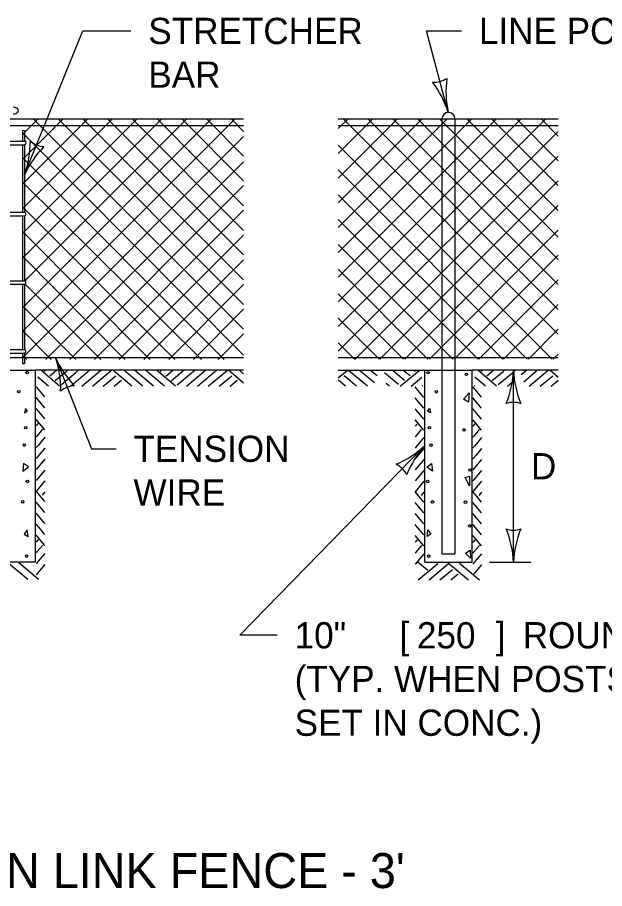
# Model space of a CAD drawing. Extents: x 49973.1 to 50021, y 49987.6 to 50015.4.
# Drawn here: x 49975.152 to 49976.495, y 50007.825 to 50009.818 of the extents above; entities that cross this region are included whole.
import ezdxf

# ---------------------------------------------------------------- set-up
doc = ezdxf.new("R2010")
doc.units = 0
for name, color, linetype in [('Level 1', 7, 'Continuous'), ('Level 2', 7, 'Continuous'), ('Level 3', 7, 'Continuous')]:
    doc.layers.add(name, color=color, linetype=linetype)

msp = doc.modelspace()

# ---------------------------------------------------------------- linework, layer by layer
at = {"layer": 'Level 1'}
for p, q in [((49973.9263, 50009.5857), (49975.6696, 50009.5857)), ((49975.1128, 50009.5707), (49975.6696, 50009.5707)), ((49975.65, 50009.5857), (49975.1633, 50009.099)), ((49975.4827, 50009.5857), (49975.1634, 50009.2664)), ((49975.4259, 50009.5857), (49975.1635, 50009.323)), ((49975.5959, 50009.5857), (49975.1636, 50009.1534)), ((49975.3696, 50009.5857), (49975.1637, 50009.3798)), ((49975.3132, 50009.5857), (49975.1638, 50009.4363)), ((49975.1999, 50009.5857), (49975.1639, 50009.5498)), ((49975.2566, 50009.5857), (49975.1641, 50009.4932)), ((49975.5395, 50009.5857), (49975.174, 50009.2202)), ((49975.6696, 50009.1047), (49975.1886, 50009.5857)), ((49975.6696, 50009.1613), (49975.2452, 50009.5857)), ((49975.6696, 50009.2179), (49975.3018, 50009.5857)), ((49975.6696, 50009.2745), (49975.3584, 50009.5857)), ((49975.6696, 50009.3308), (49975.415, 50009.5857)), ((49975.6696, 50009.3871), (49975.4716, 50009.5857)), ((49975.6696, 50009.4441), (49975.5282, 50009.5857)), ((49975.6696, 50009.5004), (49975.5846, 50009.5857)), ((49975.6696, 50009.557), (49975.6412, 50009.5857)), ((49975.886, 50009.1108), (49976.361, 50009.5857)), ((49975.886, 50009.5634), (49975.9084, 50009.5857)), ((49975.886, 50009.5068), (49975.965, 50009.5857)), ((49975.886, 50009.4502), (49976.0216, 50009.5857)), ((49975.886, 50009.2238), (49976.248, 50009.5857)), ((49975.886, 50009.337), (49976.1348, 50009.5857)), ((49975.886, 50009.2804), (49976.1914, 50009.5857)), ((49975.886, 50009.1674), (49976.3044, 50009.5857)), ((49975.886, 50009.3936), (49976.0781, 50009.5856)), ((49975.886, 50009.5856), (49976.389, 50009.5856)), ((49975.886, 50009.5707), (49976.389, 50009.5707)), ((49975.8973, 50009.5857), (49976.389, 50009.0935)), ((49975.954, 50009.5857), (49976.389, 50009.1501)), ((49976.0106, 50009.5857), (49976.389, 50009.2073)), ((49976.0671, 50009.5856), (49976.389, 50009.2641)), ((49976.1177, 50009.5857), (49976.389, 50009.3149)), ((49976.123, 50009.5856), (49976.123, 50008.5908)), ((49976.153, 50009.5856), (49976.153, 50008.5908)), ((49976.18, 50009.5857), (49976.389, 50009.3766)), ((49976.2366, 50009.5857), (49976.389, 50009.4333)), ((49976.2934, 50009.5857), (49976.389, 50009.4901)), ((49976.35, 50009.5857), (49976.389, 50009.5466)), ((49975.6696, 50009.0453), (49975.1634, 50009.5546)), ((49975.1639, 50009.5598), (49975.1689, 50009.5594)), ((49975.1639, 50009.5598), (49975.1639, 50009.5348)), ((49975.1689, 50009.5594), (49975.1689, 50009.5348)), ((49975.886, 50009.0542), (49976.389, 50009.5572)), ((49975.1132, 50009.5348), (49975.1694, 50009.5348)), ((49975.6696, 50009.5454), (49975.1638, 50009.0396)), ((49975.1132, 50009.5267), (49975.1692, 50009.5267)), ((49975.1639, 50009.5267), (49975.1639, 50009.3722)), ((49975.1689, 50009.5267), (49975.1689, 50009.3722)), ((49975.886, 50009.5256), (49976.375, 50009.0364)), ((49975.6249, 50009.0357), (49975.164, 50009.4974)), ((49975.6696, 50009.4879), (49975.2174, 50009.0357)), ((49975.9249, 50009.0364), (49976.389, 50009.5006)), ((49975.886, 50009.4689), (49976.3182, 50009.0364)), ((49975.5731, 50009.0357), (49975.1638, 50009.4409)), ((49975.6696, 50009.4333), (49975.272, 50009.0357)), ((49975.9815, 50009.0364), (49976.389, 50009.444)), ((49975.886, 50009.4124), (49976.2624, 50009.0364)), ((49975.113, 50009.3722), (49975.1692, 50009.3722)), ((49975.512, 50009.0357), (49975.1637, 50009.3845)), ((49975.6696, 50009.3767), (49975.3286, 50009.0357)), ((49976.0381, 50009.0364), (49976.389, 50009.3874)), ((49975.113, 50009.3641), (49975.169, 50009.3641)), ((49975.1639, 50009.3641), (49975.1639, 50009.2156)), ((49975.1689, 50009.3641), (49975.1689, 50009.2156)), ((49975.886, 50009.3559), (49976.2057, 50009.0364)), ((49975.4551, 50009.0357), (49975.1638, 50009.328)), ((49976.0945, 50009.0364), (49976.389, 50009.331)), ((49975.6696, 50009.3201), (49975.3852, 50009.0357)), ((49975.886, 50009.2988), (49976.148, 50009.0364)), ((49975.3978, 50009.0357), (49975.1638, 50009.2714)), ((49976.1511, 50009.0364), (49976.389, 50009.2744)), ((49975.6696, 50009.2635), (49975.4418, 50009.0357)), ((49975.886, 50009.242), (49976.0911, 50009.0364)), ((49975.113, 50009.2156), (49975.1692, 50009.2156)), ((49975.175, 50009.2212), (49975.1691, 50009.2153)), ((49976.2077, 50009.0364), (49976.389, 50009.2178)), ((49975.113, 50009.2075), (49975.169, 50009.2075)), ((49975.1639, 50009.2075), (49975.1639, 50009.058)), ((49975.1689, 50009.2075), (49975.1689, 50009.058)), ((49975.3428, 50009.0357), (49975.1704, 50009.2081)), ((49975.6696, 50009.2069), (49975.4984, 50009.0357)), ((49975.886, 50009.186), (49976.0355, 50009.0364)), ((49975.2862, 50009.0357), (49975.1636, 50009.1583)), ((49975.6696, 50009.1505), (49975.5548, 50009.0357)), ((49976.2643, 50009.0364), (49976.389, 50009.1612)), ((49975.886, 50009.1297), (49975.9793, 50009.0364)), ((49975.2296, 50009.0357), (49975.1636, 50009.1017)), ((49975.6696, 50009.0939), (49975.6114, 50009.0357)), ((49976.3209, 50009.0364), (49976.389, 50009.1046)), ((49975.886, 50009.0734), (49975.923, 50009.0364)), ((49975.1126, 50009.058), (49975.1686, 50009.058)), ((49975.1126, 50009.0499), (49975.1686, 50009.0499)), ((49975.1639, 50009.0499), (49975.1639, 50009.026)), ((49975.1689, 50009.0499), (49975.1689, 50009.0261)), ((49973.7232, 50009.0402), (49975.6696, 50009.0402)), ((49975.173, 50009.0357), (49975.1639, 50009.0449)), ((49975.886, 50009.0402), (49976.389, 50009.0402)), ((49975.9244, 50009.0359), (49975.9246, 50009.0357)), ((49975.9244, 50009.0359), (49975.9244, 50009.0357)), ((49975.9244, 50009.0359), (49975.9245, 50009.0357)), ((49975.9244, 50009.0359), (49975.9244, 50009.0357)), ((49976.3775, 50009.0364), (49976.389, 50009.048)), ((49975.0629, 50009.0109), (49975.1929, 50009.0109)), ((49975.1639, 50009.026), (49975.1689, 50009.0261)), ((49975.1852, 50009.0108), (49975.1829, 50009.0108)), ((49975.1929, 50009.0109), (49975.1929, 50008.5718)), ((49975.6696, 50009.0108), (49975.1929, 50009.0108)), ((49975.2488, 50008.9746), (49975.2059, 50009.0107)), ((49975.2138, 50009.0081), (49975.2169, 50009.0107)), ((49975.2265, 50008.9979), (49975.2419, 50009.0107)), ((49975.2636, 50009.008), (49975.2669, 50009.0107)), ((49975.2738, 50008.9746), (49975.3171, 50009.0108)), ((49975.2852, 50009.0051), (49975.292, 50009.0107)), ((49975.2995, 50008.9746), (49975.3428, 50009.0108)), ((49975.324, 50008.9746), (49975.3673, 50009.0108)), ((49975.4139, 50008.9741), (49975.3704, 50009.0107)), ((49975.4389, 50008.9741), (49975.3954, 50009.0107)), ((49975.4639, 50008.9741), (49975.4204, 50009.0107)), ((49975.4459, 50009.0102), (49975.4454, 50009.0107)), ((49975.4889, 50008.9741), (49975.4459, 50009.0102)), ((49975.5139, 50008.9741), (49975.4704, 50009.0107)), ((49975.4789, 50009.0076), (49975.4826, 50009.0107)), ((49975.4916, 50008.9974), (49975.5073, 50009.0105)), ((49975.5073, 50009.0105), (49975.5076, 50009.0107)), ((49975.5287, 50009.0075), (49975.5326, 50009.0107)), ((49975.5389, 50008.9741), (49975.5827, 50009.0107)), ((49975.5503, 50009.0046), (49975.5577, 50009.0107)), ((49975.5639, 50008.9741), (49975.6077, 50009.0107)), ((49975.5889, 50008.9741), (49975.6326, 50009.0107)), ((49975.6696, 50008.9815), (49975.6349, 50009.0107)), ((49975.6696, 50009.0025), (49975.6599, 50009.0107)), ((49975.886, 50009.0107), (49976.0838, 50009.0107)), ((49975.886, 50008.9936), (49975.9063, 50009.0106)), ((49975.9529, 50008.9745), (49975.9098, 50009.0106)), ((49975.9529, 50008.9745), (49975.9098, 50009.0106)), ((49975.9688, 50008.9821), (49975.9347, 50009.0106)), ((49975.9748, 50008.998), (49975.9597, 50009.0106)), ((49976.0131, 50009.0079), (49976.0098, 50009.0106)), ((49976.0279, 50008.9745), (49976.0708, 50009.0106)), ((49976.0502, 50008.9978), (49976.0348, 50009.0106)), ((49976.0629, 50009.008), (49976.0598, 50009.0106)), ((49976.0807, 50009.0107), (49976.083, 50009.0107)), ((49976.0838, 50009.0108), (49976.1921, 50009.0108)), ((49976.0838, 50008.5717), (49976.0838, 50009.0107)), ((49976.1921, 50008.5717), (49976.1921, 50009.0108)), ((49976.389, 50009.0108), (49976.1921, 50009.0108)), ((49976.248, 50008.9746), (49976.2051, 50009.0107)), ((49976.213, 50009.0081), (49976.2161, 50009.0107)), ((49976.2257, 50008.9979), (49976.2411, 50009.0107)), ((49976.2628, 50009.008), (49976.2661, 50009.0107)), ((49976.2844, 50009.0051), (49976.2912, 50009.0107)), ((49976.3045, 50009.0009), (49976.3162, 50009.0107)), ((49976.3101, 50008.9847), (49976.3412, 50009.0107)), ((49976.323, 50008.9746), (49976.3661, 50009.0107)), ((49976.323, 50008.9746), (49976.3661, 50009.0107)), ((49976.389, 50008.9944), (49976.3696, 50009.0107)), ((49975.2238, 50008.9746), (49975.1992, 50008.9952)), ((49975.239, 50008.9874), (49975.2636, 50009.008)), ((49975.2529, 50008.978), (49975.2852, 50009.0051)), ((49975.3488, 50008.9746), (49975.3772, 50008.9984)), ((49975.5041, 50008.9869), (49975.5287, 50009.0075)), ((49975.518, 50008.9775), (49975.5503, 50009.0046)), ((49975.6139, 50008.9741), (49975.6423, 50008.9979)), ((49975.9279, 50008.9745), (49975.8995, 50008.9983)), ((49976.0238, 50008.9779), (49975.9915, 50009.005)), ((49976.0377, 50008.9873), (49976.0131, 50009.0079)), ((49976.0529, 50008.9745), (49976.0775, 50008.9951)), ((49976.223, 50008.9746), (49976.1984, 50008.9952)), ((49976.2382, 50008.9874), (49976.2628, 50009.008)), ((49976.2521, 50008.978), (49976.2844, 50009.0051)), ((49976.348, 50008.9746), (49976.3764, 50008.9984)), ((49975.2152, 50008.9498), (49975.1953, 50008.9735)), ((49975.3738, 50008.9746), (49975.3901, 50008.9883)), ((49975.6389, 50008.9741), (49975.6552, 50008.9878)), ((49975.9029, 50008.9745), (49975.8866, 50008.9882)), ((49976.0029, 50008.9745), (49975.9955, 50008.9807)), ((49976.0816, 50008.9489), (49976.0617, 50008.9726)), ((49976.0779, 50008.9745), (49976.0792, 50008.9756)), ((49976.2139, 50008.949), (49976.194, 50008.9727)), ((49976.198, 50008.9746), (49976.1967, 50008.9757)), ((49976.273, 50008.9746), (49976.2834, 50008.9833)), ((49976.373, 50008.9746), (49976.389, 50008.9881)), ((49975.2152, 50008.9248), (49975.1953, 50008.9485)), ((49976.0816, 50008.9239), (49976.0617, 50008.9476)), ((49976.2139, 50008.924), (49976.194, 50008.9477)), ((49975.1968, 50008.9218), (49975.1953, 50008.9235)), ((49975.2152, 50008.8998), (49975.1968, 50008.9218)), ((49976.0632, 50008.9209), (49976.0617, 50008.9226)), ((49976.0816, 50008.8989), (49976.0632, 50008.9209)), ((49976.1955, 50008.921), (49976.194, 50008.9227)), ((49976.2139, 50008.899), (49976.1955, 50008.921)), ((49975.2152, 50008.8748), (49975.1953, 50008.8985)), ((49976.0816, 50008.8739), (49976.0617, 50008.8976)), ((49976.2139, 50008.874), (49976.194, 50008.8977)), ((49975.1994, 50008.8888), (49975.1952, 50008.8838)), ((49975.2096, 50008.8761), (49975.1965, 50008.8604)), ((49976.0658, 50008.8879), (49976.0616, 50008.8829)), ((49976.076, 50008.8752), (49976.0629, 50008.8595)), ((49976.1981, 50008.888), (49976.1939, 50008.883)), ((49976.2083, 50008.8753), (49976.1952, 50008.8596)), ((49975.1965, 50008.8604), (49975.1953, 50008.8589)), ((49975.2152, 50008.8577), (49975.1995, 50008.839)), ((49976.0629, 50008.8595), (49976.0617, 50008.858)), ((49976.0816, 50008.8568), (49976.0659, 50008.8381)), ((49976.1952, 50008.8596), (49976.194, 50008.8581)), ((49976.2139, 50008.8569), (49976.1982, 50008.8382)), ((49975.1995, 50008.839), (49975.1953, 50008.8339)), ((49975.2152, 50008.8326), (49975.2024, 50008.8174)), ((49976.0659, 50008.8381), (49976.0617, 50008.833)), ((49976.0816, 50008.8317), (49976.0688, 50008.8165)), ((49976.1982, 50008.8382), (49976.194, 50008.8331)), ((49976.2139, 50008.8318), (49976.2011, 50008.8166)), ((49975.2024, 50008.8174), (49975.1953, 50008.8088)), ((49976.0688, 50008.8165), (49976.0617, 50008.8079)), ((49976.2011, 50008.8166), (49976.194, 50008.808)), ((49975.2152, 50008.8076), (49975.1953, 50008.7838)), ((49976.0816, 50008.8067), (49976.0617, 50008.7829)), ((49976.2139, 50008.8068), (49976.194, 50008.783)), ((49975.2152, 50008.7826), (49975.1953, 50008.7588)), ((49976.0816, 50008.7817), (49976.0617, 50008.7579)), ((49976.2139, 50008.7818), (49976.194, 50008.758)), ((49975.2152, 50008.7577), (49975.1953, 50008.734)), ((49976.0816, 50008.7568), (49976.0617, 50008.7331)), ((49976.2139, 50008.7569), (49976.194, 50008.7332)), ((49975.2152, 50008.7103), (49975.1953, 50008.734)), ((49975.2152, 50008.7326), (49975.2091, 50008.7254)), ((49976.0816, 50008.7094), (49976.0617, 50008.7331)), ((49976.0816, 50008.7317), (49976.0755, 50008.7245)), ((49976.2139, 50008.7095), (49976.194, 50008.7332)), ((49976.2139, 50008.7318), (49976.2078, 50008.7246)), ((49975.2152, 50008.6853), (49975.1953, 50008.709)), ((49976.0816, 50008.6844), (49976.0617, 50008.7081)), ((49976.2139, 50008.6845), (49976.194, 50008.7082)), ((49975.2152, 50008.6603), (49975.1953, 50008.684)), ((49976.0816, 50008.6594), (49976.0617, 50008.6831)), ((49976.2139, 50008.6595), (49976.194, 50008.6832)), ((49975.1973, 50008.6567), (49975.1953, 50008.659)), ((49975.2152, 50008.6353), (49975.1973, 50008.6567)), ((49976.0637, 50008.6558), (49976.0617, 50008.6581)), ((49976.0816, 50008.6344), (49976.0637, 50008.6558)), ((49976.196, 50008.6559), (49976.194, 50008.6582)), ((49976.2139, 50008.6345), (49976.196, 50008.6559)), ((49975.2152, 50008.6103), (49975.1953, 50008.634)), ((49976.0816, 50008.6094), (49976.0617, 50008.6331)), ((49976.2139, 50008.6095), (49976.194, 50008.6332)), ((49975.1957, 50008.6187), (49975.1953, 50008.6182)), ((49975.1999, 50008.6237), (49975.1957, 50008.6187)), ((49975.2101, 50008.611), (49975.197, 50008.5953)), ((49976.0621, 50008.6178), (49976.0617, 50008.6173)), ((49976.0663, 50008.6228), (49976.0621, 50008.6178)), ((49976.1944, 50008.6179), (49976.194, 50008.6174)), ((49976.1986, 50008.6229), (49976.1944, 50008.6179)), ((49975.197, 50008.5953), (49975.1953, 50008.5932)), ((49975.2152, 50008.592), (49975.2, 50008.5739)), ((49976.0634, 50008.5944), (49976.0617, 50008.5923)), ((49976.0765, 50008.6101), (49976.0634, 50008.5944)), ((49976.0816, 50008.5911), (49976.0664, 50008.573)), ((49976.123, 50008.5908), (49976.153, 50008.5908)), ((49976.138, 50008.5908), (49976.138, 50008.5902)), ((49976.1957, 50008.5945), (49976.194, 50008.5924)), ((49976.2088, 50008.6102), (49976.1957, 50008.5945)), ((49976.2139, 50008.5912), (49976.1987, 50008.5731)), ((49975.1929, 50008.5718), (49975.0629, 50008.5718)), ((49975.2, 50008.5739), (49975.1953, 50008.5682)), ((49976.0664, 50008.573), (49976.0617, 50008.5673)), ((49976.0906, 50008.5529), (49976.0682, 50008.5717)), ((49976.0838, 50008.5717), (49976.1921, 50008.5717)), ((49976.1987, 50008.5731), (49976.194, 50008.5674)), ((49975.1759, 50008.5325), (49975.1306, 50008.5706)), ((49975.2009, 50008.5325), (49975.1556, 50008.5706)), ((49975.2029, 50008.5523), (49975.1953, 50008.5431)), ((49975.2152, 50008.5669), (49975.2029, 50008.5523)), ((49976.0686, 50008.5312), (49976.1136, 50008.5688)), ((49976.0936, 50008.5312), (49976.1384, 50008.5688)), ((49976.1186, 50008.5312), (49976.147, 50008.555)), ((49976.1837, 50008.5307), (49976.1384, 50008.5688)), ((49976.2087, 50008.5307), (49976.1634, 50008.5688)), ((49976.2016, 50008.5515), (49976.194, 50008.5423)), ((49976.2139, 50008.5661), (49976.2016, 50008.5515)), ((49976.1436, 50008.5312), (49976.1599, 50008.5449))]:
    msp.add_line(p, q, dxfattribs=at)
for points in [[(49976.1728, 50008.9445), (49976.1852, 50008.9589), (49976.1838, 50008.9377)], [(49975.1754, 50008.9172), (49975.1706, 50008.9234), (49975.1686, 50008.9138)], [(49976.0905, 50008.9171), (49976.0953, 50008.9233), (49976.0973, 50008.9137)], [(49975.1775, 50008.7896), (49975.1665, 50008.7978), (49975.1644, 50008.7799)], [(49976.0884, 50008.7895), (49976.0994, 50008.7977), (49976.1015, 50008.7798)], [(49976.1762, 50008.7654), (49976.1858, 50008.7689), (49976.1865, 50008.7462)], [(49975.1768, 50008.6304), (49975.1747, 50008.6461), (49975.1679, 50008.6359)], [(49976.0891, 50008.6303), (49976.0912, 50008.646), (49976.098, 50008.6358)], [(49976.1769, 50008.5925), (49976.1879, 50008.5994), (49976.1886, 50008.5809)]]:
    msp.add_lwpolyline(points, close=True, dxfattribs=at)
for centre in [(49975.1747, 50009.0056), (49976.0912, 50009.0055), (49976.179, 50009.0014), (49975.1555, 50008.9617), (49976.1104, 50008.9616), (49975.1713, 50008.8794), (49976.0946, 50008.8793), (49976.1735, 50008.8745), (49975.1679, 50008.8396), (49976.098, 50008.8395), (49976.1872, 50008.7825), (49975.1754, 50008.7565), (49976.0905, 50008.7564), (49975.1644, 50008.7099), (49976.1015, 50008.7098), (49976.177, 50008.7091), (49976.1866, 50008.6549), (49975.1733, 50008.5857), (49976.0926, 50008.5856)]:
    msp.add_circle(centre, 0.00279, dxfattribs=at)
for centre, radius, start, end in [((49976.138, 50009.5856), 0.015, 2.6745, 180.7625), ((49975.168, 50009.5309), 0.00417, 282.5816, 72.0167), ((49975.1678, 50009.3683), 0.00417, 282.5816, 72.0167), ((49975.1678, 50009.2117), 0.00417, 282.5816, 72.0167), ((49975.1674, 50009.0541), 0.00417, 282.5816, 72.0167)]:
    msp.add_arc(centre, radius, start, end, dxfattribs=at)
msp.add_ellipse((49975.143, 50009.6048), major_axis=(0.0115, -0.0001), ratio=0.649749, start_param=4.712389, end_param=7.853982, dxfattribs=at)
at = {"layer": 'Level 3'}
for p, q in [((49975.1689, 50009.4583), (49975.3022, 50009.7869)), ((49975.3022, 50009.7869), (49975.4117, 50009.7869)), ((49976.0882, 50009.7869), (49976.1678, 50009.7869)), ((49976.1375, 50009.6006), (49976.0882, 50009.7869)), ((49975.2394, 50009.0402), (49975.3216, 50008.8313)), ((49976.2868, 50008.5718), (49976.2868, 50009.0108)), ((49975.3216, 50008.8313), (49975.3778, 50008.8313)), ((49975.6607, 50008.4047), (49976.0838, 50008.8384)), ((49976.2321, 50008.5718), (49976.3268, 50008.5718)), ((49975.7463, 50008.4047), (49975.6607, 50008.4047))]:
    msp.add_line(p, q, dxfattribs=at)
for centre, radius, start, end in [((49976.1047, 50009.7246), 0.0548, 266.9596, 302.682), ((49975.9155, 50009.53), 0.233, 17.6481, 36.898), ((49976.3546, 50009.6486), 0.2223, 172.2768, 192.4603), ((49974.9489, 50009.5352), 0.233, 340.7469, 359.9967), ((49975.217, 50009.5771), 0.0548, 230.0584, 265.7807), ((49975.3713, 50009.3663), 0.2223, 135.3756, 155.5591), ((49975.029, 50008.9684), 0.2223, 358.6766, 18.8602), ((49975.4521, 50009.1352), 0.233, 204.048, 223.2978), ((49976.0541, 50009.0223), 0.233, 337.9228, 357.1727), ((49976.509, 50009.02), 0.2223, 182.3605, 202.544), ((49975.2858, 50008.9207), 0.0548, 93.3595, 129.0818), ((49976.2868, 50008.8826), 0.0548, 72.1388, 107.8612), ((49975.9312, 50009.0001), 0.2223, 293.1632, 313.3468), ((49976.2584, 50008.6842), 0.233, 138.5345, 157.7844), ((49975.9943, 50008.7467), 0.0548, 27.8461, 63.5684), ((49976.0647, 50008.5627), 0.2223, 2.3605, 22.544), ((49976.2868, 50008.7), 0.0548, 252.1388, 287.8612), ((49976.5195, 50008.5603), 0.233, 157.9228, 177.1727)]:
    msp.add_arc(centre, radius, start, end, dxfattribs=at)

# ---------------------------------------------------------------- texts
at = {"layer": 'Level 2'}
for s, height, p in [('STRETCHER', 0.06, (49975.4517, 50009.7569)), ('LINE POST', 0.06, (49976.2078, 50009.7569)), ('BAR', 0.06, (49975.4517, 50009.6569)), ('TENSION', 0.06, (49975.4178, 50008.8013)), ('D', 0.06, (49976.3268, 50008.7613)), ('WIRE', 0.06, (49975.4178, 50008.7013)), ('10" ', 0.06, (49975.7863, 50008.3747)), ('[', 0.06, (49976.0263, 50008.3747)), ('250', 0.06, (49976.066, 50008.3747)), (']', 0.06, (49976.246, 50008.3747)), (' ROUND SECT.', 0.06, (49976.2857, 50008.3747)), ('(TYP. WHEN POSTS', 0.06, (49975.7863, 50008.2747)), ('SET IN CONC.)', 0.06, (49975.7863, 50008.1747)), ("CHAIN LINK FENCE - 3' ", 0.08, (49974.8705, 50007.8265))]:
    msp.add_text(s, height=height, dxfattribs=at).set_placement(p)

doc.saveas('drawing.dxf')
